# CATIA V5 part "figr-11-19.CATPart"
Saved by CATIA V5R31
Part number: Part1
Bounding box of the stored display mesh (mm): x -112.891 to 155.069, y -166 to 177, z -20.381 to 17.354
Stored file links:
  D:\PROJECTS\Project 2021\US EDITION\CATIA V5 6R 2021\Resources\Part Files\c11_catia_v5_6r2021_prt\figr-11-19.CATPart
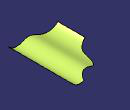
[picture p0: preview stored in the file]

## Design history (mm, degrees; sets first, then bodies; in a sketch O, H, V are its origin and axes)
Set1
  Sketch1 on zx-plane, origin (0, 0, 0), H (-1, 0, 0), V (0, 0, 1)
    spline S1 through (-155.0686, 17.3535) (-88.0787, 0) (-53.6625, 10.5338) (-6.5258, 0) (112.8909, 0)
    point P1 (-88.0787, 0)
    point P2 (-6.5258, 0)
    point P3 (112.8909, 0)
    coincidence: P1 H, P2 H, P3 H
  Extrude1: Element1 Sketch1, Lim1 177, Lim2 166, Direction zx-plane
  Sketch2 on xy-plane, origin (0, 0, 0), H (1, 0, 0), V (0, 1, 0)
    spline S1 through (-167.4699, -22.0252) (-66.0833, 12.4475) (-43.2893, 80.3989) (-11.0164, 123.7609) (37.393, 134.2276) (93.5198, 192.542)
  Extrude2: Element1 Sketch2, Lim1 94, Lim2 109, Direction xy-plane
  Trim1: Element1 Extrude1, Element2 Extrude2
  DatumSurface1
  DatumSurface2
  StUntrimFeature1 "CATStUntrimFeatureName": SpecToUntrim DatumSurface1
Body1 (main body)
